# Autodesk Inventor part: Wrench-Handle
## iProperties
Created: 2005-01
Part Number: Wrench-Handle
Document SubType Name: Modeling
Designer: Dale Schneider
Manufacturer: Standard
Standards Organization: Custom
Density: 1 g/cm^3
Stock Number: Wrench-Handle
Author: Dale Schneider
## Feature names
1. Extrusion1
2. Fillet1
3. Fillet2
4. Fillet3
5. Extrusion2
6. Hole1
7. Extrusion3
